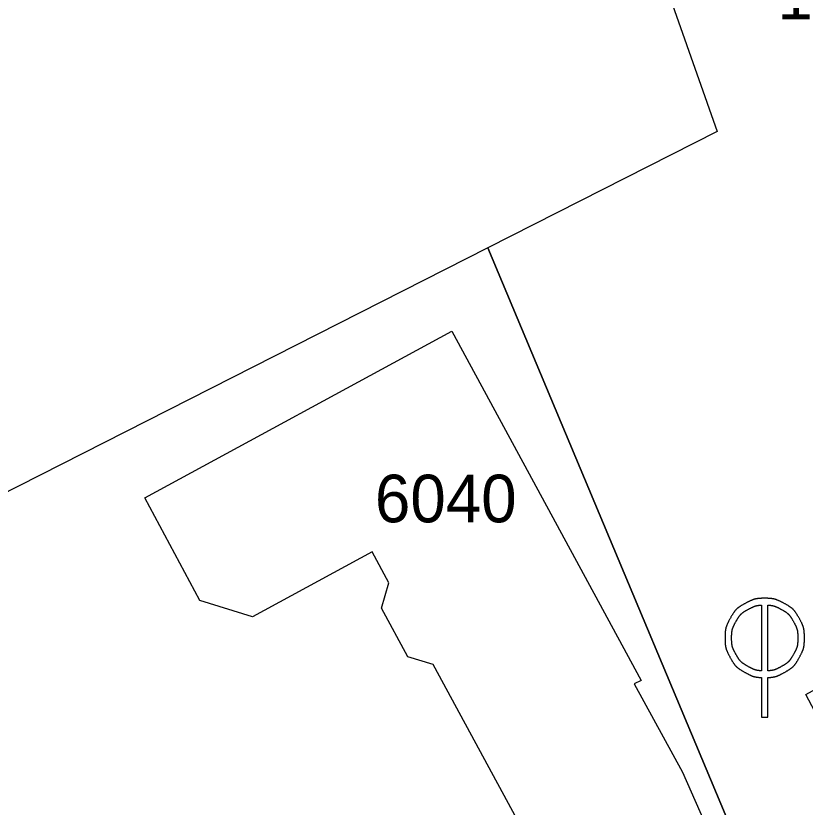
# Model space of a CAD drawing. Extents: x -562248 to -562040, y -1079385 to -1079027.
# Drawn here: x -562140.7 to -562115.84, y -1079267.68 to -1079242.75 of the extents above; entities that cross this region are included whole.
import ezdxf

# ---------------------------------------------------------------- set-up
doc = ezdxf.new("R2010")
doc.units = 0
for name, color, linetype in [('Default', 7, 'Continuous'), ('Kanalizační šachta', 7, 'Continuous'), ('Parcela-polygon', 7, 'Continuous'), ('Parcela-text', 7, 'Continuous')]:
    doc.layers.add(name, color=color, linetype=linetype)

msp = doc.modelspace()

# ---------------------------------------------------------------- linework, layer by layer
at = {"layer": 'Default'}
for points in [[(-562117.116, -1079261.102), (-562117.328, -1079261.102), (-562117.533, -1079261.156), (-562117.731, -1079261.264)], [(-562116.502, -1079261.264), (-562116.702, -1079261.156), (-562116.906, -1079261.102), (-562117.116, -1079261.102)], [(-562117.731, -1079261.264), (-562117.93, -1079261.371), (-562118.085, -1079261.525), (-562118.198, -1079261.725)], [(-562118.02, -1079261.831), (-562117.927, -1079261.664), (-562117.797, -1079261.536), (-562117.631, -1079261.447)], [(-562117.631, -1079261.447), (-562117.488, -1079261.37), (-562117.351, -1079261.326), (-562117.219, -1079261.315)], [(-562117.014, -1079261.315), (-562116.882, -1079261.326), (-562116.745, -1079261.37), (-562116.604, -1079261.447)], [(-562116.604, -1079261.447), (-562116.438, -1079261.536), (-562116.308, -1079261.664), (-562116.214, -1079261.831)], [(-562116.035, -1079261.725), (-562116.147, -1079261.525), (-562116.303, -1079261.371), (-562116.502, -1079261.264)], [(-562118.198, -1079261.725), (-562118.31, -1079261.925), (-562118.366, -1079262.134), (-562118.366, -1079262.352)], [(-562118.159, -1079262.352), (-562118.159, -1079262.172), (-562118.112, -1079261.998), (-562118.02, -1079261.831)], [(-562116.214, -1079261.831), (-562116.121, -1079261.998), (-562116.074, -1079262.172), (-562116.074, -1079262.352)], [(-562115.866, -1079262.352), (-562115.866, -1079262.134), (-562115.922, -1079261.925), (-562116.035, -1079261.725)], [(-562118.366, -1079262.352), (-562118.366, -1079262.569), (-562118.311, -1079262.776), (-562118.201, -1079262.975)], [(-562118.022, -1079262.87), (-562118.113, -1079262.706), (-562118.159, -1079262.533), (-562118.159, -1079262.352)], [(-562116.074, -1079262.352), (-562116.074, -1079262.533), (-562116.119, -1079262.706), (-562116.21, -1079262.87)], [(-562116.031, -1079262.975), (-562115.921, -1079262.776), (-562115.866, -1079262.569), (-562115.866, -1079262.352)], [(-562117.636, -1079263.253), (-562117.802, -1079263.162), (-562117.931, -1079263.034), (-562118.022, -1079262.87)], [(-562116.21, -1079262.87), (-562116.302, -1079263.034), (-562116.429, -1079263.162), (-562116.594, -1079263.253)], [(-562118.201, -1079262.975), (-562118.092, -1079263.174), (-562117.937, -1079263.327), (-562117.739, -1079263.436)], [(-562116.494, -1079263.436), (-562116.295, -1079263.327), (-562116.141, -1079263.174), (-562116.031, -1079262.975)], [(-562117.739, -1079263.436), (-562117.565, -1079263.534), (-562117.391, -1079263.589), (-562117.219, -1079263.6)], [(-562117.219, -1079263.388), (-562117.355, -1079263.378), (-562117.495, -1079263.333), (-562117.636, -1079263.253)], [(-562116.594, -1079263.253), (-562116.737, -1079263.333), (-562116.877, -1079263.378), (-562117.014, -1079263.388)], [(-562117.014, -1079263.6), (-562116.841, -1079263.589), (-562116.668, -1079263.534), (-562116.494, -1079263.436)]]:
    msp.add_open_spline(points, degree=2, dxfattribs=at)
at = {"layer": 'Kanalizační šachta'}
for points in [[(-562117.219, -1079261.315), (-562117.219, -1079263.388)], [(-562117.014, -1079263.388), (-562117.014, -1079261.315)], [(-562117.219, -1079264.852), (-562117.014, -1079264.852), (-562117.014, -1079263.6)], [(-562117.219, -1079263.6), (-562117.219, -1079264.852)]]:
    msp.add_lwpolyline(points, dxfattribs=at)
at = {"layer": 'Parcela-polygon'}
msp.add_line((-562125.839, -1079250.062), (-562150.955, -1079262.816), dxfattribs=at)
for points in [[(-562125.839, -1079250.062), (-562115.46, -1079274.84), (-562111.34, -1079272.6), (-562115.82, -1079264.13), (-562111.86, -1079261.96), (-562112.48, -1079260.84), (-562109.81, -1079259.38), (-562109.2, -1079260.5), (-562101.14, -1079256.08), (-562102.73, -1079253.17), (-562100.18, -1079251.98), (-562102.28, -1079247.51), (-562108.03, -1079234.16), (-562113.76, -1079220.84), (-562114.87, -1079218.31), (-562116.77, -1079219.12), (-562123.59, -1079221.97), (-562126.807, -1079223.131)], [(-562126.807, -1079223.131), (-562118.618, -1079246.395), (-562125.839, -1079250.062)], [(-562150.955, -1079262.816), (-562144.68, -1079274.39), (-562135.96, -1079290.46), (-562131.57, -1079288.07), (-562113.94, -1079278.46), (-562115.46, -1079274.84), (-562125.839, -1079250.062)], [(-562128.35, -1079262.95), (-562129.18, -1079261.41), (-562128.95, -1079260.62), (-562129.48, -1079259.64), (-562133.24, -1079261.69), (-562134.9, -1079261.17), (-562136.63, -1079257.94), (-562126.97, -1079252.69), (-562121.01, -1079263.69), (-562121.23, -1079263.8), (-562119.71, -1079266.58), (-562115.88, -1079275.25), (-562118.9, -1079276.84), (-562119.32, -1079277.09), (-562119.43, -1079276.92), (-562128.39, -1079281.65), (-562132.65, -1079273.7), (-562132.78, -1079273.77), (-562133, -1079273.36), (-562124.5, -1079268.83), (-562127.56, -1079263.19), (-562128.35, -1079262.95)]]:
    msp.add_lwpolyline(points, dxfattribs=at)
msp.add_lwpolyline([(-562129.18, -1079261.41), (-562128.95, -1079260.62), (-562129.48, -1079259.64), (-562133.24, -1079261.69), (-562134.9, -1079261.17), (-562136.63, -1079257.94), (-562126.97, -1079252.69), (-562121.01, -1079263.69), (-562121.23, -1079263.8), (-562119.71, -1079266.58), (-562115.88, -1079275.25), (-562118.9, -1079276.84), (-562123.54, -1079268.32), (-562124.5, -1079268.83), (-562127.56, -1079263.19), (-562128.35, -1079262.95)], close=True, dxfattribs=at)

# ---------------------------------------------------------------- texts
at = {"layer": 'Parcela-text'}
for s, p in [('1346/8', (-562116.72, -1079242.87)), ('6040', (-562129.39, -1079258.71))]:
    msp.add_text(s, height=1.5, dxfattribs=at).set_placement(p)

doc.saveas('drawing.dxf')
